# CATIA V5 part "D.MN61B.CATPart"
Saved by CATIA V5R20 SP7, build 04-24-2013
Part number: D.MN61B
Revision: 00.0
Material "Nessuno"
Bounding box of the stored display mesh (mm): x 0 to 150.807, y -131.181 to 0, z -91.151 to 75.737
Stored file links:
  C:\Users\designer2\Desktop\Ottobre 2022\25-10-2022\04\Yori Evo 48V\D.MN61B.CATPart
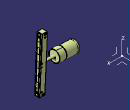
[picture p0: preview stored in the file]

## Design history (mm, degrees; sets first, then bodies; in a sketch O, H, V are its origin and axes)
AxisSystem1: origin (0, 0, 0), X (1, 0, 0), Y (0, 1, 0), Z (0, 0, 1)
Set1
  DatumSurface1
Body1 (main body), material "Nessuno"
